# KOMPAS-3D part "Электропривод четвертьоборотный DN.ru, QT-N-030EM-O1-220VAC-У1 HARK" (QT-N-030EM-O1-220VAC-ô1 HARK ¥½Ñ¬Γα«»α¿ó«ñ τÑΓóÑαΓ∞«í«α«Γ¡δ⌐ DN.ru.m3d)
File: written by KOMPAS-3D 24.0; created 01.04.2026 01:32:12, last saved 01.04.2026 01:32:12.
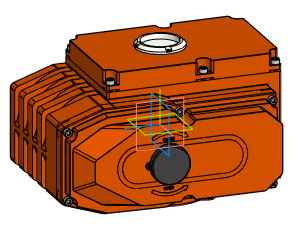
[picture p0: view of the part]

Document properties: Автор: DN.RU; Полное имя файла: D:\PROJECT CAD\DN.RU\...195\Исходники\220В\QT-N-030EM-O1-220VAC-У1 HARK Электропривод четвертьоборотный DN.ru\QT-N-030EM-O1-220VAC-У1 HARK Электропривод четвертьоборотный DN.ru.m3d

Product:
- Body: Твердое тело1  | qty 1
    Масса: 37.407802
- Part/product: Электропривод четвертьоборотный DN.ru  | designation QT-N-030EM-O1-220VAC-У1 HARK
    Масса: 8.9
    Раздел спецификации: Прочие изделия
    Комментарий: D300-05872
    Примечание: D300-05872
    additional columns: Сталь

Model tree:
1. Твердое тело1  (labels: Твердое тело1)

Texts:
  QT-N-030EM-O1-220VAC-У1 HARK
